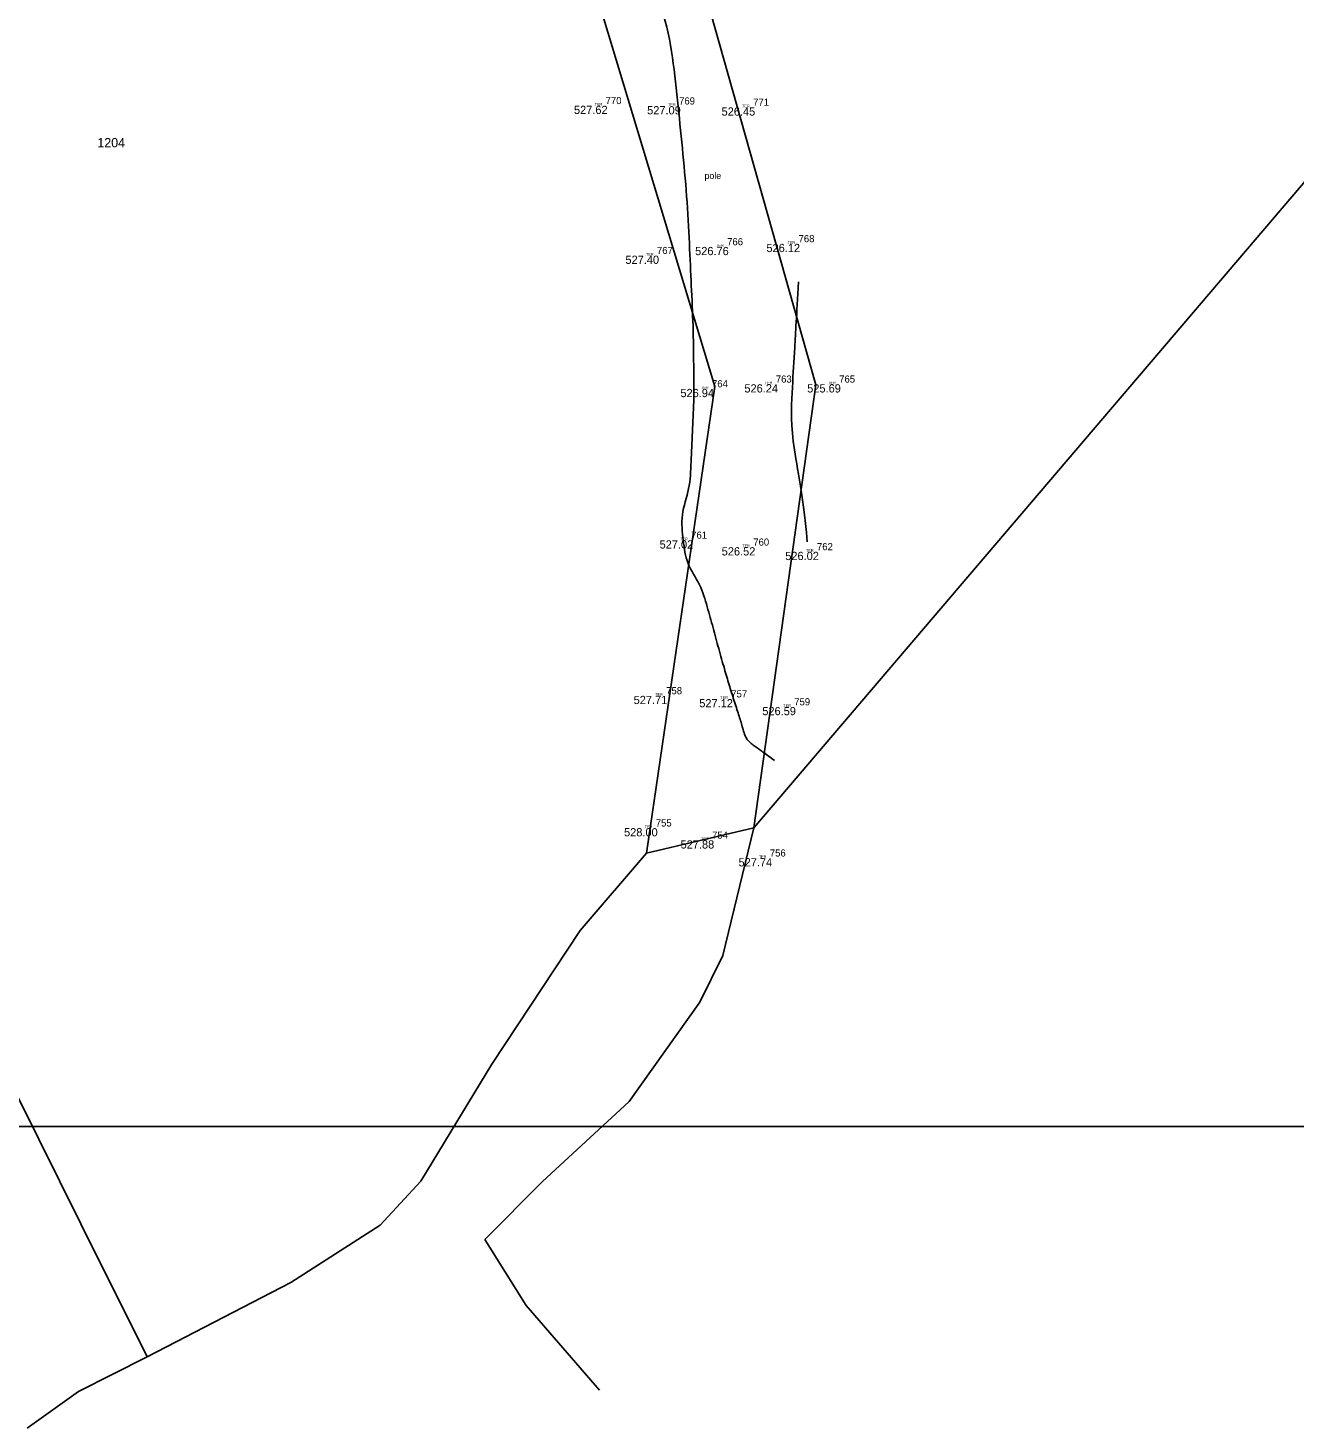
# Model space of a CAD drawing. Extents: x -604848 to -603227, y -1111879 to -1109838.
# Drawn here: x -604243.7 to -604012.5, y -1111477.8 to -1111222.3 of the extents above; entities that cross this region are included whole.
import ezdxf

# ---------------------------------------------------------------- set-up
doc = ezdxf.new("R2010")
doc.units = 0
for name, color, linetype in [('1', 7, 'Continuous'), ('14', 7, 'Continuous'), ('18', 7, 'Continuous'), ('19', 7, 'Continuous'), ('20', 7, 'Continuous'), ('7', 7, 'Continuous'), ('9', 7, 'Continuous'), ('Default', 7, 'Continuous')]:
    doc.layers.add(name, color=color, linetype=linetype)

# ---------------------------------------------------------------- blocks, each defined once
blk = doc.blocks.new('POINT_DISPLAY')
at = {"layer": 'Default'}
blk.add_line((0, 0), (0, 0), dxfattribs=at)

msp = doc.modelspace()

# ---------------------------------------------------------------- linework, layer by layer
at = {"layer": '1'}
for p, q in [((-604166.66, -1111127.93), (-604118.37, -1111287.69)), ((-604099.95, -1111287.39), (-604120.55, -1111214.55)), ((-603992.97, -1111229.45), (-604111.25, -1111368.25)), ((-604234.05, -1111440.49), (-604313.77, -1111280.06)), ((-604118.37, -1111287.69), (-604130.87, -1111372.89)), ((-604111.25, -1111368.25), (-604099.95, -1111287.39)), ((-604111.25, -1111368.25), (-604130.87, -1111372.89)), ((-604116.93, -1111391.53), (-604111.25, -1111368.25)), ((-604130.87, -1111372.89), (-604142.93, -1111387.01)), ((-604142.93, -1111387.01), (-604159.04, -1111411.39)), ((-604121.14, -1111400.06), (-604116.93, -1111391.53)), ((-604134.04, -1111418.22), (-604121.14, -1111400.06)), ((-604159.04, -1111411.39), (-604172.03, -1111432.7)), ((-604149.89, -1111432.86), (-604134.04, -1111418.22)), ((-604172.03, -1111432.7), (-604179.43, -1111440.74)), ((-604160.32, -1111443.38), (-604149.89, -1111432.86)), ((-604221.97, -1111464.8), (-604234.05, -1111440.49)), ((-604179.43, -1111440.74), (-604195.72, -1111451.21)), ((-604152.78, -1111455.4), (-604160.32, -1111443.38)), ((-604195.72, -1111451.21), (-604221.97, -1111464.8)), ((-604139.42, -1111470.87), (-604152.78, -1111455.4)), ((-604221.97, -1111464.8), (-604234.49, -1111471.1)), ((-604234.49, -1111471.1), (-604243.84, -1111477.77))]:
    msp.add_line(p, q, dxfattribs=at)
msp.add_lwpolyline([(-603781.41, -1111422.77), (-603781.41, -1110582.77), (-604375.41, -1110582.77), (-604375.41, -1111422.77), (-603781.41, -1111422.77)], dxfattribs=at)
at = {"layer": '7'}
for points in [[(-604107.47, -1111355.96), (-604108.69, -1111355.09), (-604109.9, -1111354.22), (-604111.11, -1111353.34), (-604112.81, -1111352.11), (-604113.35, -1111349.73), (-604114, -1111347.73), (-604114.9, -1111344.93), (-604115.79, -1111342.15), (-604116.6, -1111339.33), (-604117.69, -1111335.55), (-604118.69, -1111331.74), (-604119.76, -1111327.96), (-604120.92, -1111323.84), (-604123.63, -1111320.08), (-604124.13, -1111315.85), (-604124.69, -1111311.14), (-604122.89, -1111306.36), (-604122.71, -1111301.58), (-604122.5, -1111296.04), (-604122.18, -1111290.5), (-604122.23, -1111284.96), (-604122.29, -1111277.59), (-604122.63, -1111270.22), (-604122.97, -1111262.85), (-604123.38, -1111254.08), (-604124.18, -1111245.34), (-604125.08, -1111236.59), (-604126, -1111227.67), (-604127.68, -1111218.79), (-604131.66, -1111210.53), (-604135.98, -1111201.59), (-604142.42, -1111194.28), (-604147.23, -1111185.91), (-604151.95, -1111177.72), (-604153.4, -1111167.07), (-604160.35, -1111160.57), (-604163.55, -1111157.58), (-604166.75, -1111154.58), (-604169.95, -1111151.59)], [(-604101.51, -1111316.08), (-604102.4, -1111306.49), (-604104.76, -1111296.91), (-604104.2, -1111287.31), (-604103.84, -1111281.08), (-604103.47, -1111274.84), (-604103.11, -1111268.6)]]:
    msp.add_open_spline(points, degree=3, dxfattribs=at)

# ---------------------------------------------------------------- block references
at = {"layer": '18'}
for p in [(-604140.31, -1111236.49), (-604126.91, -1111236.56), (-604113.4, -1111236.79), (-604118.14, -1111262.25), (-604105.11, -1111261.69), (-604130.94, -1111263.84), (-604120.9, -1111288.16), (-604109.26, -1111287.31), (-604097.7, -1111287.31), (-604124.7, -1111315.79), (-604113.37, -1111317.05), (-604101.75, -1111317.89), (-604129.26, -1111344.17), (-604117.39, -1111344.76), (-604105.9, -1111346.2), (-604131.16, -1111368.31), (-604120.89, -1111370.53), (-604110.35, -1111373.79)]:
    msp.add_blockref('POINT_DISPLAY', p, dxfattribs=at)

# ---------------------------------------------------------------- texts
at = {"layer": '14'}
msp.add_text('1204', height=1.7, dxfattribs=at).set_placement((-604231.03, -1111244.07))
at = {"layer": '18'}
for p in [(-604140.31, -1111236.49), (-604126.91, -1111236.56), (-604113.4, -1111236.79), (-604130.94, -1111263.84), (-604118.14, -1111262.25), (-604105.11, -1111261.69), (-604120.9, -1111288.16), (-604109.26, -1111287.31), (-604097.7, -1111287.31), (-604124.7, -1111315.79), (-604113.37, -1111317.05), (-604101.75, -1111317.89), (-604129.26, -1111344.17), (-604117.39, -1111344.76), (-604105.9, -1111346.2), (-604131.16, -1111368.31), (-604120.89, -1111370.53), (-604110.35, -1111373.79)]:
    msp.add_text('TER', height=0.5, dxfattribs=at).set_placement(p)
at = {"layer": '19'}
for s, p in [('770', (-604138.31, -1111236.19)), ('769', (-604124.91, -1111236.26)), ('771', (-604111.4, -1111236.49)), ('766', (-604116.14, -1111261.95)), ('768', (-604103.11, -1111261.39)), ('767', (-604128.94, -1111263.54)), ('763', (-604107.26, -1111287.01)), ('765', (-604095.7, -1111287.01)), ('764', (-604118.9, -1111287.86)), ('761', (-604122.7, -1111315.49)), ('760', (-604111.37, -1111316.75)), ('762', (-604099.75, -1111317.59)), ('758', (-604127.26, -1111343.87)), ('757', (-604115.39, -1111344.46)), ('759', (-604103.9, -1111345.9)), ('755', (-604129.16, -1111368.01)), ('754', (-604118.89, -1111370.23)), ('756', (-604108.35, -1111373.49))]:
    msp.add_text(s, height=1.3, dxfattribs=at).set_placement(p)
at = {"layer": '20'}
for s, p in [('527.62 ', (-604144.08, -1111237.99)), ('527.09 ', (-604130.73, -1111238.06)), ('526.45 ', (-604117.15, -1111238.29)), ('526.76 ', (-604121.98, -1111263.75)), ('526.12 ', (-604108.97, -1111263.19)), ('527.40 ', (-604134.69, -1111265.34)), ('526.94 ', (-604124.66, -1111289.66)), ('526.24 ', (-604112.99, -1111288.81)), ('525.69 ', (-604101.53, -1111288.81)), ('527.02 ', (-604128.46, -1111317.29)), ('526.52 ', (-604117.13, -1111318.55)), ('526.02 ', (-604105.53, -1111319.39)), ('527.71 ', (-604133.19, -1111345.67)), ('527.12 ', (-604121.22, -1111346.26)), ('526.59 ', (-604109.72, -1111347.7)), ('528.00 ', (-604134.94, -1111369.81)), ('527.88 ', (-604124.63, -1111372.03)), ('527.74 ', (-604114.06, -1111375.29))]:
    msp.add_text(s, height=1.5, dxfattribs=at).set_placement(p)
at = {"layer": '9'}
msp.add_text('pole', height=1.2, dxfattribs=at).set_placement((-604120.26, -1111249.85))

doc.saveas('drawing.dxf')
